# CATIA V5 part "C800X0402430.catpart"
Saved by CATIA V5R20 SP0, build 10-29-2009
Part number: C800X0402430
Source: Unknown
Property "A": "40"
Property "ARTICLENO": "C800X0402430"
Property "B": "18"
Property "BOMINFO": "C800X0402430"
Property "C": "70"
Property "CA": "C800X0402430"
Property "D1": "58"
Property "DES": "ROTATING EYEBOLT WITH RING Ton 4,0 M24x30"
Property "E": "68"
Property "H": "153"
Property "L": "30"
Property "LINA": "C800X0402430"
Property "NB": "C800X0402430"
Property "NBSYN": "$CODE."
Property "NN": "C800X"
Property "NT": "Rotating eyebolt with ring"
Property "SIZE": "M24"
Property "SUPPLIER": "CF"
Property "SW": "48"
Property "WEIGHT": "1630"
Property "WLL": "4.00"
Bounding box of the stored display mesh (mm): x -38 to 38, y -30 to 171, z -29 to 29
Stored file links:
  C:\Users\Utente\Desktop\3D files 800X\C800X0402430.catpart

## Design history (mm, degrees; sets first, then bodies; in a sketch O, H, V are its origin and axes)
Body1 "Geometry.1" (main body)
  Solid1 "C800X0402430.catpart": solid without history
